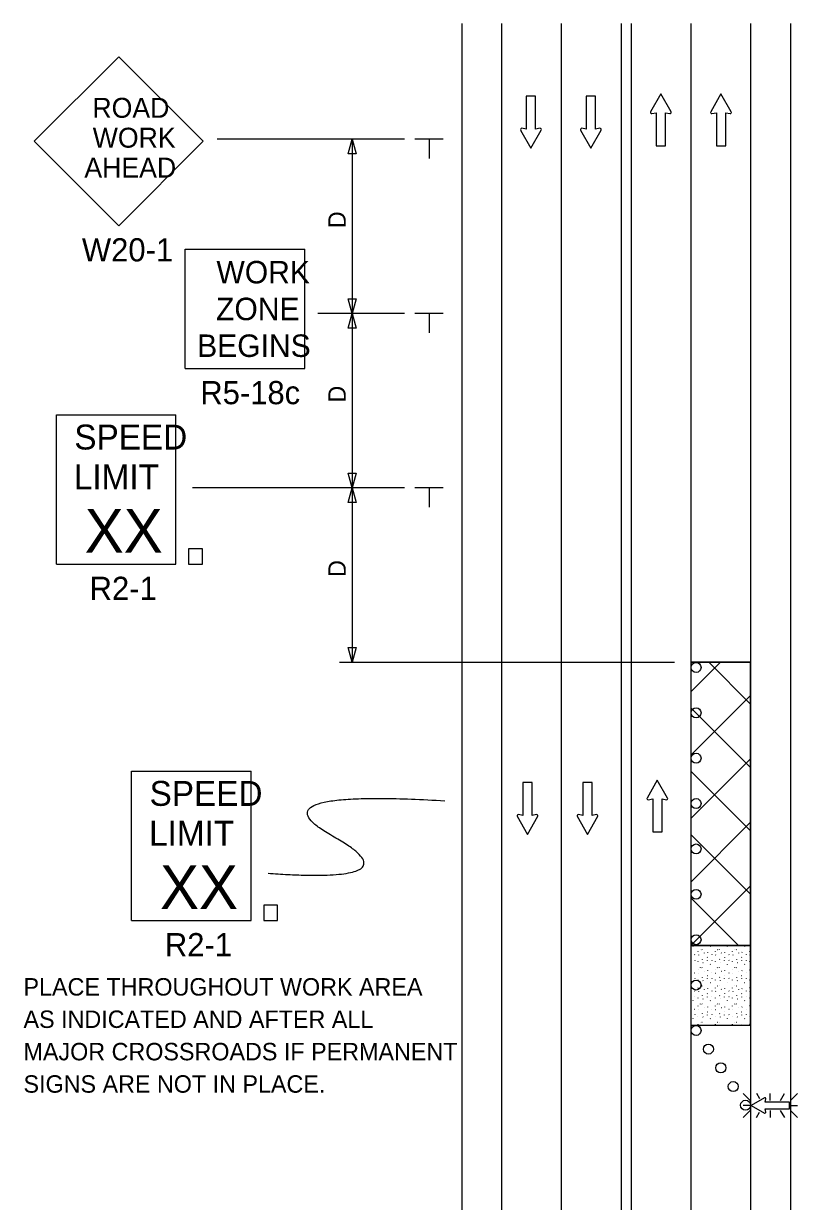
# Model space of a CAD drawing. Extents: x 16739 to 18475, y 7218 to 8197.
# Drawn here: x 16747.2 to 17058, y 7711 to 8183.9 of the extents above; entities that cross this region are included whole.
import ezdxf

# ---------------------------------------------------------------- set-up
doc = ezdxf.new("R2010")
doc.units = 0
for name, color, linetype in [('ALI_LEGAL_EX', 7, 'Continuous'), ('MT_SCRATCH_LEVEL_E', 7, 'Continuous'), ('PAVT_EDGE_EX', 7, 'Continuous'), ('TRAFFIC_SIGNS_PR', 7, 'Continuous'), ('TYPICAL_TEXT_DIMEN_PR', 7, 'Continuous')]:
    doc.layers.add(name, color=color, linetype=linetype)

msp = doc.modelspace()

# ---------------------------------------------------------------- linework, layer by layer
at = {"layer": 'ALI_LEGAL_EX'}
for points in [[(16963.15, 8183.87), (16963.15, 8158.87)], [(17015.15, 8183.87), (17015.15, 8158.87)], [(16963.15, 8083.87), (16963.15, 8058.87)], [(17015.15, 8083.87), (17015.15, 8058.87)], [(16963.15, 7983.87), (16963.15, 7958.87)], [(17015.15, 7983.87), (17015.15, 7958.87)], [(16963.15, 7883.87), (16963.15, 7858.87)], [(17015.15, 7883.87), (17015.15, 7858.87)], [(16963.15, 7783.87), (16963.15, 7758.87)], [(17015.15, 7783.87), (17015.15, 7758.87)]]:
    msp.add_lwpolyline(points, dxfattribs=at)
at = {"layer": 'MT_SCRATCH_LEVEL_E'}
for p, q in [((16949.08, 8154.76), (16949.08, 8141.5)), ((16952.82, 8154.76), (16949.08, 8154.76)), ((16952.82, 8141.5), (16952.82, 8154.76)), ((16973.15, 8154.76), (16973.15, 8141.5)), ((16976.89, 8154.76), (16973.15, 8154.76)), ((16976.89, 8141.5), (16976.89, 8154.76)), ((17003.09, 8155.7), (16998.98, 8148.46)), ((17007.23, 8148.46), (17003.09, 8155.7)), ((17027.26, 8155.7), (17023.15, 8148.46)), ((17031.4, 8148.46), (17027.26, 8155.7)), ((16999.46, 8147.78), (17001.24, 8148.09)), ((17001.24, 8148.09), (17001.24, 8134.84)), ((17004.98, 8134.84), (17004.98, 8148.09)), ((17004.98, 8148.09), (17006.76, 8147.78)), ((17023.63, 8147.78), (17025.41, 8148.09)), ((17025.41, 8148.09), (17025.41, 8134.84)), ((17029.15, 8134.84), (17029.15, 8148.09)), ((17029.15, 8148.09), (17030.93, 8147.78)), ((16946.82, 8141.13), (16950.97, 8133.89)), ((16949.08, 8141.5), (16947.3, 8141.82)), ((16950.97, 8133.89), (16955.08, 8141.13)), ((16954.6, 8141.82), (16952.82, 8141.5)), ((16970.9, 8141.13), (16975.04, 8133.89)), ((16973.15, 8141.5), (16971.37, 8141.82)), ((16975.04, 8133.89), (16979.15, 8141.13)), ((16978.67, 8141.82), (16976.89, 8141.5)), ((17001.24, 8134.84), (17004.98, 8134.84)), ((17025.41, 8134.84), (17029.15, 8134.84)), ((16947.68, 7879.26), (16947.68, 7866)), ((16951.42, 7879.26), (16947.68, 7879.26)), ((16951.42, 7866), (16951.42, 7879.26)), ((16971.75, 7879.26), (16971.75, 7866)), ((16975.5, 7879.26), (16971.75, 7879.26)), ((16975.5, 7866), (16975.5, 7879.26)), ((17001.69, 7880.2), (16997.58, 7872.96)), ((17005.84, 7872.96), (17001.69, 7880.2)), ((16998.06, 7872.28), (16999.84, 7872.6)), ((16999.84, 7872.6), (16999.84, 7859.34)), ((17003.58, 7859.34), (17003.58, 7872.6)), ((17003.58, 7872.6), (17005.36, 7872.28)), ((16945.43, 7865.63), (16949.57, 7858.39)), ((16947.68, 7866), (16945.91, 7866.32)), ((16949.57, 7858.39), (16953.68, 7865.63)), ((16953.2, 7866.32), (16951.42, 7866)), ((16969.5, 7865.63), (16973.64, 7858.39)), ((16971.75, 7866), (16969.98, 7866.32)), ((16973.64, 7858.39), (16977.75, 7865.63)), ((16977.27, 7866.32), (16975.5, 7866)), ((16999.84, 7859.34), (17003.58, 7859.34))]:
    msp.add_line(p, q, dxfattribs=at)
for centre, start, end in [((16999.38, 8148.24), 150.4248, 279.9638), ((17006.83, 8148.24), 260.0362, 29.7731), ((17023.55, 8148.24), 150.4248, 279.9638), ((17031, 8148.24), 260.0362, 29.7731), ((16947.23, 8141.36), 80.0362, 209.7731), ((16954.67, 8141.36), 330.4248, 99.9638), ((16971.3, 8141.36), 80.0362, 209.7731), ((16978.75, 8141.36), 330.4248, 99.9638), ((16997.99, 7872.74), 150.4248, 279.9638), ((17005.43, 7872.74), 260.0362, 29.7731), ((16945.84, 7865.86), 80.0362, 209.7731), ((16953.28, 7865.86), 330.4248, 99.9638), ((16969.91, 7865.86), 80.0362, 209.7731), ((16977.35, 7865.86), 330.4248, 99.9638)]:
    msp.add_arc(centre, 0.463, start, end, dxfattribs=at)
at = {"layer": 'PAVT_EDGE_EX'}
for p, q in [((16923.15, 8183.87), (16923.15, 7354.69)), ((16939.15, 8183.87), (16939.15, 7354.69)), ((16963.15, 8183.87), (16963.15, 7354.69)), ((16987.15, 8183.87), (16987.15, 7354.69)), ((16991.15, 8183.87), (16991.15, 7354.69)), ((17015.15, 8183.87), (17015.15, 7354.69)), ((17039.15, 8183.87), (17039.15, 7354.69)), ((17055.15, 8183.87), (17055.15, 7354.69)), ((17039.15, 7927.5), (17015.15, 7927.5)), ((17015.15, 7927.5), (17039.15, 7927.5)), ((17015.15, 7915.6), (17027.06, 7927.5)), ((17039.15, 7910.69), (17022.34, 7927.5)), ((17039.15, 7813.78), (17039.15, 7927.5)), ((17015.15, 7890.15), (17039.15, 7914.15)), ((17039.15, 7885.24), (17015.15, 7909.24)), ((17015.15, 7864.69), (17039.15, 7888.69)), ((17039.15, 7859.78), (17015.15, 7883.78)), ((17015.15, 7839.24), (17039.15, 7863.24)), ((17039.15, 7834.33), (17015.15, 7858.33)), ((17015.15, 7813.78), (17039.15, 7837.78)), ((17034.24, 7813.78), (17015.15, 7832.87)), ((17015.15, 7813.78), (17039.15, 7813.78)), ((17015.15, 7813.78), (17039.15, 7813.78)), ((17039.15, 7813.78), (17015.15, 7813.78)), ((17015.15, 7813.78), (17015.15, 7813.78)), ((17016.08, 7813.42), (17016.13, 7813.54)), ((17018.86, 7812.18), (17018.92, 7812.11)), ((17019.6, 7812.15), (17019.65, 7812.08)), ((17022.97, 7813.42), (17023.02, 7813.54)), ((17025.75, 7812.18), (17025.8, 7812.11)), ((17026.49, 7812.15), (17026.54, 7812.08)), ((17029.85, 7813.42), (17029.91, 7813.54)), ((17032.64, 7812.18), (17032.69, 7812.11)), ((17033.38, 7812.15), (17033.43, 7812.08)), ((17036.74, 7813.42), (17036.8, 7813.54)), ((17039.15, 7781.72), (17039.15, 7813.78)), ((17016.65, 7810.1), (17016.7, 7810.02)), ((17016.7, 7807.89), (17016.75, 7807.81)), ((17017.98, 7807.31), (17017.99, 7807.2)), ((17018.1, 7811.22), (17018.15, 7811.34)), ((17018.18, 7809.96), (17018.23, 7809.88)), ((17019.82, 7808.17), (17019.87, 7808.28)), ((17020.01, 7806.97), (17020.06, 7806.89)), ((17020.47, 7810.78), (17020.52, 7810.7)), ((17021.75, 7809.04), (17021.8, 7808.96)), ((17021.79, 7807.64), (17021.84, 7807.75)), ((17021.92, 7810.93), (17021.97, 7811.04)), ((17023.54, 7810.1), (17023.59, 7810.02)), ((17023.59, 7807.89), (17023.64, 7807.81)), ((17024.87, 7807.31), (17024.88, 7807.2)), ((17024.99, 7811.22), (17025.04, 7811.34)), ((17025.07, 7809.96), (17025.12, 7809.88)), ((17026.71, 7808.17), (17026.76, 7808.28)), ((17026.9, 7806.97), (17026.95, 7806.89)), ((17027.36, 7810.78), (17027.41, 7810.7)), ((17028.64, 7809.04), (17028.69, 7808.96)), ((17028.68, 7807.64), (17028.73, 7807.75)), ((17028.81, 7810.93), (17028.86, 7811.04)), ((17030.42, 7810.1), (17030.48, 7810.02)), ((17030.47, 7807.89), (17030.53, 7807.81)), ((17031.76, 7807.31), (17031.77, 7807.2)), ((17031.88, 7811.22), (17031.93, 7811.34)), ((17031.96, 7809.96), (17032.01, 7809.88)), ((17033.6, 7808.17), (17033.65, 7808.28)), ((17033.78, 7806.97), (17033.84, 7806.89)), ((17034.24, 7810.78), (17034.3, 7810.7)), ((17035.52, 7809.04), (17035.57, 7808.96)), ((17035.56, 7807.64), (17035.62, 7807.75)), ((17035.69, 7810.93), (17035.75, 7811.04)), ((17037.31, 7810.1), (17037.36, 7810.02)), ((17037.36, 7807.89), (17037.41, 7807.81)), ((17038.64, 7807.31), (17038.66, 7807.2)), ((17038.76, 7811.22), (17038.81, 7811.34)), ((17038.84, 7809.96), (17038.89, 7809.88)), ((17016.65, 7802.81), (17016.7, 7802.74)), ((17018.1, 7803.94), (17018.15, 7804.06)), ((17018.18, 7802.67), (17018.23, 7802.6)), ((17018.86, 7804.9), (17018.92, 7804.82)), ((17019.6, 7804.87), (17019.65, 7804.79)), ((17020.47, 7803.49), (17020.52, 7803.41)), ((17021.92, 7803.64), (17021.97, 7803.76)), ((17022.97, 7806.14), (17023.02, 7806.25)), ((17023.54, 7802.81), (17023.59, 7802.74)), ((17024.99, 7803.94), (17025.04, 7804.06)), ((17025.07, 7802.67), (17025.12, 7802.6)), ((17025.75, 7804.9), (17025.8, 7804.82)), ((17026.49, 7804.87), (17026.54, 7804.79)), ((17027.36, 7803.49), (17027.41, 7803.41)), ((17028.81, 7803.64), (17028.86, 7803.76)), ((17029.85, 7806.14), (17029.91, 7806.25)), ((17030.42, 7802.81), (17030.48, 7802.74)), ((17031.88, 7803.94), (17031.93, 7804.06)), ((17031.96, 7802.67), (17032.01, 7802.6)), ((17032.64, 7804.9), (17032.69, 7804.82)), ((17033.38, 7804.87), (17033.43, 7804.79)), ((17034.24, 7803.49), (17034.3, 7803.41)), ((17035.69, 7803.64), (17035.75, 7803.76)), ((17036.74, 7806.14), (17036.8, 7806.25)), ((17037.31, 7802.81), (17037.36, 7802.74)), ((17038.76, 7803.94), (17038.81, 7804.06)), ((17038.84, 7802.67), (17038.89, 7802.6)), ((17016.08, 7798.85), (17016.13, 7798.97)), ((17016.7, 7800.6), (17016.75, 7800.53)), ((17017.98, 7800.03), (17017.99, 7799.91)), ((17018.86, 7797.61), (17018.92, 7797.54)), ((17019.6, 7797.59), (17019.65, 7797.51)), ((17019.82, 7800.88), (17019.87, 7801)), ((17020.01, 7799.69), (17020.06, 7799.61)), ((17021.75, 7801.75), (17021.8, 7801.68)), ((17021.79, 7800.35), (17021.84, 7800.47)), ((17022.97, 7798.85), (17023.02, 7798.97)), ((17023.59, 7800.6), (17023.64, 7800.53)), ((17024.87, 7800.03), (17024.88, 7799.91)), ((17025.75, 7797.61), (17025.8, 7797.54)), ((17026.49, 7797.59), (17026.54, 7797.51)), ((17026.71, 7800.88), (17026.76, 7801)), ((17026.9, 7799.69), (17026.95, 7799.61)), ((17028.64, 7801.75), (17028.69, 7801.68)), ((17028.68, 7800.35), (17028.73, 7800.47)), ((17029.85, 7798.85), (17029.91, 7798.97)), ((17030.47, 7800.6), (17030.53, 7800.53)), ((17031.76, 7800.03), (17031.77, 7799.91)), ((17032.64, 7797.61), (17032.69, 7797.54)), ((17033.38, 7797.59), (17033.43, 7797.51)), ((17033.6, 7800.88), (17033.65, 7801)), ((17033.78, 7799.69), (17033.84, 7799.61)), ((17035.52, 7801.75), (17035.57, 7801.68)), ((17035.56, 7800.35), (17035.62, 7800.47)), ((17036.74, 7798.85), (17036.8, 7798.97)), ((17037.36, 7800.6), (17037.41, 7800.53)), ((17038.64, 7800.03), (17038.66, 7799.91)), ((17016.65, 7795.53), (17016.7, 7795.45)), ((17016.7, 7793.32), (17016.75, 7793.24)), ((17017.98, 7792.74), (17017.99, 7792.63)), ((17018.1, 7796.65), (17018.15, 7796.77)), ((17018.18, 7795.39), (17018.23, 7795.31)), ((17019.82, 7793.6), (17019.87, 7793.72)), ((17020.47, 7796.21), (17020.52, 7796.13)), ((17021.75, 7794.47), (17021.8, 7794.39)), ((17021.79, 7793.07), (17021.84, 7793.19)), ((17021.92, 7796.36), (17021.97, 7796.47)), ((17023.54, 7795.53), (17023.59, 7795.45)), ((17023.59, 7793.32), (17023.64, 7793.24)), ((17024.87, 7792.74), (17024.88, 7792.63)), ((17024.99, 7796.65), (17025.04, 7796.77)), ((17025.07, 7795.39), (17025.12, 7795.31)), ((17026.71, 7793.6), (17026.76, 7793.72)), ((17027.36, 7796.21), (17027.41, 7796.13)), ((17028.64, 7794.47), (17028.69, 7794.39)), ((17028.68, 7793.07), (17028.73, 7793.19)), ((17028.81, 7796.36), (17028.86, 7796.47)), ((17030.42, 7795.53), (17030.48, 7795.45)), ((17030.47, 7793.32), (17030.53, 7793.24)), ((17031.76, 7792.74), (17031.77, 7792.63)), ((17031.88, 7796.65), (17031.93, 7796.77)), ((17031.96, 7795.39), (17032.01, 7795.31)), ((17033.6, 7793.6), (17033.65, 7793.72)), ((17034.24, 7796.21), (17034.3, 7796.13)), ((17035.52, 7794.47), (17035.57, 7794.39)), ((17035.56, 7793.07), (17035.62, 7793.19)), ((17035.69, 7796.36), (17035.75, 7796.47)), ((17037.31, 7795.53), (17037.36, 7795.45)), ((17037.36, 7793.32), (17037.41, 7793.24)), ((17038.64, 7792.74), (17038.66, 7792.63)), ((17038.76, 7796.65), (17038.81, 7796.77)), ((17038.84, 7795.39), (17038.89, 7795.31)), ((17016.08, 7791.57), (17016.13, 7791.68)), ((17016.65, 7788.24), (17016.7, 7788.17)), ((17018.1, 7789.37), (17018.15, 7789.49)), ((17018.18, 7788.1), (17018.23, 7788.03)), ((17018.86, 7790.33), (17018.92, 7790.25)), ((17019.6, 7790.3), (17019.65, 7790.22)), ((17020.01, 7792.4), (17020.06, 7792.32)), ((17020.47, 7788.92), (17020.52, 7788.84)), ((17021.92, 7789.07), (17021.97, 7789.19)), ((17022.97, 7791.57), (17023.02, 7791.68)), ((17023.54, 7788.24), (17023.59, 7788.17)), ((17024.99, 7789.37), (17025.04, 7789.49)), ((17025.07, 7788.1), (17025.12, 7788.03)), ((17025.75, 7790.33), (17025.8, 7790.25)), ((17026.49, 7790.3), (17026.54, 7790.22)), ((17026.9, 7792.4), (17026.95, 7792.32)), ((17027.36, 7788.92), (17027.41, 7788.84)), ((17028.81, 7789.07), (17028.86, 7789.19)), ((17029.85, 7791.57), (17029.91, 7791.68)), ((17030.42, 7788.24), (17030.48, 7788.17)), ((17031.88, 7789.37), (17031.93, 7789.49)), ((17031.96, 7788.1), (17032.01, 7788.03)), ((17032.64, 7790.33), (17032.69, 7790.25)), ((17033.38, 7790.3), (17033.43, 7790.22)), ((17033.78, 7792.4), (17033.84, 7792.32)), ((17034.24, 7788.92), (17034.3, 7788.84)), ((17035.69, 7789.07), (17035.75, 7789.19)), ((17036.74, 7791.57), (17036.8, 7791.68)), ((17037.31, 7788.24), (17037.36, 7788.17)), ((17038.76, 7789.37), (17038.81, 7789.49)), ((17038.84, 7788.1), (17038.89, 7788.03)), ((17016.08, 7784.28), (17016.13, 7784.4)), ((17016.7, 7786.03), (17016.75, 7785.96)), ((17017.98, 7785.46), (17017.99, 7785.34)), ((17019.82, 7786.31), (17019.87, 7786.43)), ((17020.01, 7785.11), (17020.06, 7785.04)), ((17021.75, 7787.18), (17021.8, 7787.11)), ((17021.79, 7785.78), (17021.84, 7785.9)), ((17022.97, 7784.28), (17023.02, 7784.4)), ((17023.59, 7786.03), (17023.64, 7785.96)), ((17024.87, 7785.46), (17024.88, 7785.34)), ((17026.71, 7786.31), (17026.76, 7786.43)), ((17026.9, 7785.11), (17026.95, 7785.04)), ((17028.64, 7787.18), (17028.69, 7787.11)), ((17028.68, 7785.78), (17028.73, 7785.9)), ((17029.85, 7784.28), (17029.91, 7784.4)), ((17030.47, 7786.03), (17030.53, 7785.96)), ((17031.76, 7785.46), (17031.77, 7785.34)), ((17033.6, 7786.31), (17033.65, 7786.43)), ((17033.78, 7785.11), (17033.84, 7785.04)), ((17035.52, 7787.18), (17035.57, 7787.11)), ((17035.56, 7785.78), (17035.62, 7785.9)), ((17036.74, 7784.28), (17036.8, 7784.4)), ((17037.36, 7786.03), (17037.41, 7785.96)), ((17038.64, 7785.46), (17038.66, 7785.34)), ((17015.15, 7781.72), (17039.15, 7781.72)), ((17015.15, 7781.72), (17039.15, 7781.72)), ((17018.1, 7782.09), (17018.15, 7782.2)), ((17018.86, 7783.05), (17018.92, 7782.97)), ((17019.6, 7783.02), (17019.65, 7782.94)), ((17021.92, 7781.79), (17021.97, 7781.9)), ((17024.99, 7782.09), (17025.04, 7782.2)), ((17025.75, 7783.05), (17025.8, 7782.97)), ((17026.49, 7783.02), (17026.54, 7782.94)), ((17028.81, 7781.79), (17028.86, 7781.9)), ((17031.88, 7782.09), (17031.93, 7782.2)), ((17032.64, 7783.05), (17032.69, 7782.97)), ((17033.38, 7783.02), (17033.43, 7782.94)), ((17035.69, 7781.79), (17035.75, 7781.9)), ((17038.76, 7782.09), (17038.81, 7782.2))]:
    msp.add_line(p, q, dxfattribs=at)
at = {"layer": 'TRAFFIC_SIGNS_PR'}
for p, q in [((16785.45, 8170.57), (16751.51, 8136.63)), ((16819.39, 8136.63), (16785.45, 8170.57)), ((16751.51, 8136.63), (16785.45, 8102.69)), ((16785.45, 8102.69), (16819.39, 8136.63)), ((16812.18, 8045.35), (16812.18, 8093.35)), ((16812.18, 8093.35), (16860.18, 8093.35)), ((16860.18, 8045.35), (16860.18, 8093.35)), ((16812.18, 8045.35), (16860.18, 8045.35)), ((16760.42, 8026.8), (16808.42, 8026.8)), ((16760.42, 7966.8), (16760.42, 8026.8)), ((16808.42, 7966.8), (16808.42, 8026.8)), ((16760.42, 7966.8), (16808.42, 7966.8)), ((16790.63, 7883.75), (16838.63, 7883.75)), ((16790.63, 7823.75), (16790.63, 7883.75)), ((16838.63, 7823.75), (16838.63, 7883.75)), ((16790.63, 7823.75), (16838.63, 7823.75)), ((17036.14, 7754.41), (17038.96, 7751.59)), ((17042.86, 7752.23), (17041.6, 7754.41)), ((17047.05, 7751.59), (17047.05, 7754.41)), ((17051.18, 7751.59), (17052.81, 7754.41)), ((17055.13, 7751.59), (17057.95, 7754.41)), ((17038.96, 7749.56), (17036.14, 7749.56)), ((17036.14, 7744.71), (17038.96, 7747.53)), ((17041.58, 7744.71), (17042.78, 7746.8)), ((17047.05, 7747.53), (17047.05, 7744.71)), ((17052.83, 7744.71), (17051.21, 7747.53)), ((17055.13, 7749.56), (17057.95, 7749.56)), ((17055.13, 7747.53), (17057.95, 7744.71))]:
    msp.add_line(p, q, dxfattribs=at)
for points in [[(16813.43, 7966.8), (16819.03, 7966.8), (16819.03, 7972.97), (16813.43, 7972.97)], [(16843.65, 7823.75), (16849.24, 7823.75), (16849.24, 7829.92), (16843.65, 7829.92)]]:
    msp.add_lwpolyline(points, close=True, dxfattribs=at)
for points in [[(17044.72, 7752.58), (17039.41, 7749.56), (17044.72, 7746.52)], [(17045.22, 7746.88), (17044.99, 7748.18), (17054.71, 7748.18), (17054.71, 7750.92), (17044.99, 7750.92), (17045.22, 7752.22)]]:
    msp.add_lwpolyline(points, dxfattribs=at)
for centre in [(17017.25, 7925.38), (17017.25, 7907.17), (17017.25, 7888.95), (17017.25, 7870.74), (17017.25, 7852.53), (17017.25, 7834.31), (17017.25, 7816.1), (17017.25, 7797.88), (17017.25, 7779.67), (17022.22, 7772.16), (17027.19, 7764.65), (17032.16, 7757.15), (17037.13, 7749.64)]:
    msp.add_circle(centre, 2, dxfattribs=at)
for centre, start, end in [((17044.89, 7752.28), 350.7308, 118.8916), ((17044.88, 7746.82), 241.4833, 9.9593)]:
    msp.add_arc(centre, 0.341, start, end, dxfattribs=at)
msp.add_open_spline([(16845.39, 7842.74), (16905.76, 7838.48), (16837.29, 7876.64), (16916.35, 7871.89)], degree=2, dxfattribs=at)
at = {"layer": 'TYPICAL_TEXT_DIMEN_PR'}
for p, q in [((16900.15, 8137.5), (16824.95, 8137.5)), ((16877.58, 8131.64), (16879.15, 8137.5)), ((16879.15, 8137.5), (16879.15, 8067.5)), ((16879.15, 8137.5), (16880.72, 8131.64)), ((16915.65, 8137.5), (16904.4, 8137.5)), ((16910.03, 8137.5), (16910.03, 8129.72)), ((16879.15, 8131.64), (16877.58, 8131.64)), ((16880.72, 8131.64), (16879.15, 8131.64)), ((16879.15, 8067.5), (16877.58, 8073.37)), ((16877.58, 8073.37), (16879.15, 8073.37)), ((16879.15, 8073.37), (16880.72, 8073.37)), ((16880.72, 8073.37), (16879.15, 8067.5)), ((16900.15, 8067.5), (16865.4, 8067.5)), ((16877.58, 8061.64), (16879.15, 8067.5)), ((16879.15, 8067.5), (16879.15, 7997.5)), ((16879.15, 8067.5), (16880.72, 8061.64)), ((16915.65, 8067.5), (16904.4, 8067.5)), ((16910.03, 8067.5), (16910.03, 8059.72)), ((16879.15, 8061.64), (16877.58, 8061.64)), ((16880.72, 8061.64), (16879.15, 8061.64)), ((16879.15, 7997.5), (16877.58, 8003.37)), ((16877.58, 8003.37), (16879.15, 8003.37)), ((16879.15, 8003.37), (16880.72, 8003.37)), ((16880.72, 8003.37), (16879.15, 7997.5)), ((16900.15, 7997.5), (16815.05, 7997.5)), ((16877.58, 7991.64), (16879.15, 7997.5)), ((16879.15, 7997.5), (16879.15, 7927.5)), ((16879.15, 7997.5), (16880.72, 7991.64)), ((16915.65, 7997.5), (16904.4, 7997.5)), ((16910.03, 7997.5), (16910.03, 7989.72)), ((16879.15, 7991.64), (16877.58, 7991.64)), ((16880.72, 7991.64), (16879.15, 7991.64)), ((16879.15, 7927.5), (16877.58, 7933.37)), ((16877.58, 7933.37), (16879.15, 7933.37)), ((16879.15, 7933.37), (16880.72, 7933.37)), ((16880.72, 7933.37), (16879.15, 7927.5)), ((16874.15, 7927.5), (17008.54, 7927.5))]:
    msp.add_line(p, q, dxfattribs=at)

# ---------------------------------------------------------------- texts
at = {"layer": 'TRAFFIC_SIGNS_PR'}
for s, height, p in [('ROAD', 8, (16774.88, 8146.05)), ('WORK', 8, (16775.01, 8134.05)), ('AHEAD', 8, (16771.65, 8122.05)), ('W20-1', 9.3, (16770.66, 8088.39)), ('WORK', 9.021, (16824.68, 8079.56)), ('ZONE', 9.021, (16824.53, 8064.8)), ('BEGINS', 9.021, (16816.94, 8050.04)), ('R5-18c', 9.3, (16818.2, 8031.06)), ('SPEED', 10, (16767.62, 8012.88)), ('LIMIT', 10, (16767.42, 7996.88)), ('XX', 17.538, (16771.81, 7971.5)), ('R2-1', 9.3, (16773.76, 7952.5)), ('SPEED', 10, (16797.84, 7869.83)), ('LIMIT', 10, (16797.64, 7853.83)), ('XX', 17.538, (16802.03, 7828.45)), ('R2-1', 9.3, (16803.98, 7809.45)), ('PLACE THROUGHOUT WORK AREA', 7, (16747.22, 7793.67)), ('AS INDICATED AND AFTER ALL', 7, (16747.22, 7780.67)), ('MAJOR CROSSROADS IF PERMANENT', 7, (16747.22, 7767.67)), ('SIGNS ARE NOT IN PLACE.', 7, (16747.22, 7754.67))]:
    msp.add_text(s, height=height, dxfattribs=at).set_placement(p)
at = {"layer": 'TYPICAL_TEXT_DIMEN_PR'}
for p in [(16876.59, 8101.72), (16876.59, 8031.72), (16876.59, 7961.72)]:
    msp.add_text('D', height=7, rotation=90, dxfattribs=at).set_placement(p)

doc.saveas('drawing.dxf')
